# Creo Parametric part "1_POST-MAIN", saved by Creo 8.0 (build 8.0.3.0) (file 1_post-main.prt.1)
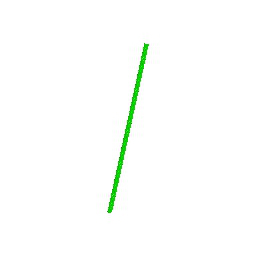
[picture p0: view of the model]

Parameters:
  SMT_DFLT_BEND_REL_LENGTH_TYPE = "Through All"

Other parameters: SMT_UPDATE_BEND_ALLOW_INFO, SMT_THICKNESS, SMT_PART_BEND_ALLOWANCE_FACTOR, SMT_DFLT_BEND_RADIUS, SMT_DFLT_BEND_ANGLE, SMT_DFLT_CRNR_REL_WIDTH, SMT_DFLT_CRNR_REL_DEPTH, SMT_DFLT_BEND_REL_WIDTH, SMT_DFLT_BEND_REL_DEPTH, SMT_DFLT_BEND_REL_LENGTH, SMT_DFLT_BEND_REL_ANGLE, SMT_GAP, SMT_DFLT_EDGE_TREA_WIDTH, SMT_DFLT_MITER_CUT_WIDTH, SMT_DFLT_MITER_CUT_OFFSET

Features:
  1. datum plane "RIGHT"
  2. datum plane "TOP"
  3. datum plane "FRONT"
  4. coordinate system
  5. pattern
  6. cut
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
Layers: 0_ALL_AXES, 0_ALL_AXIS, 0_ALL_CSYS, 0_ALL_CURVES, 0_ALL_PLANES, 0_ALL_POINTS, 0_ALL_SURFS, POST-MAIN

Surfaces: 662 plane, 175 cylinder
